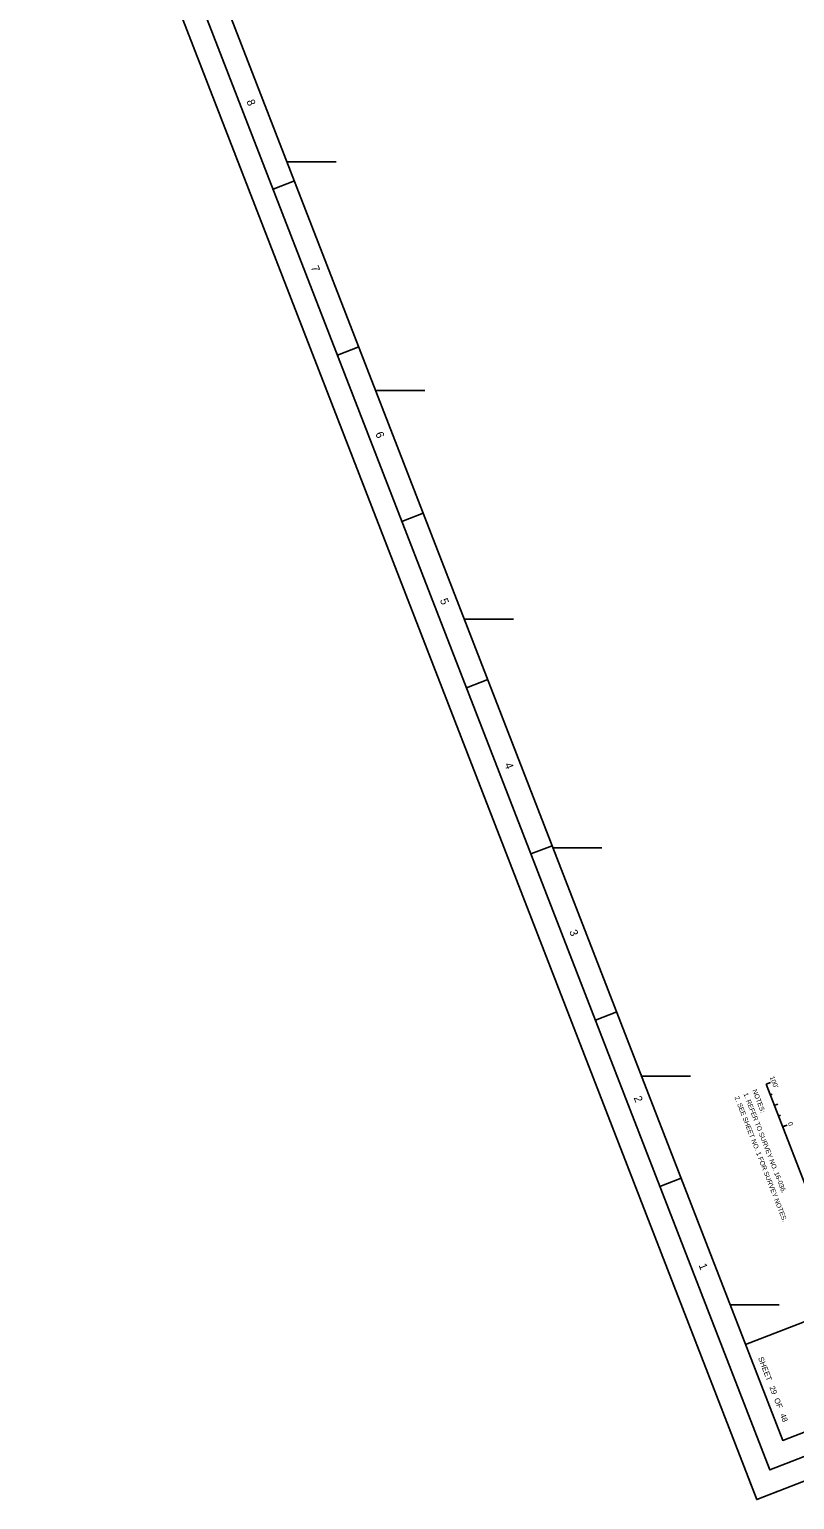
# Model space of a CAD drawing. Extents: x 587779 to 592541, y 824574 to 829906.
# Drawn here: x 587779 to 589454, y 824574 to 827790 of the extents above; entities that cross this region are included whole.
import ezdxf

# ---------------------------------------------------------------- set-up
doc = ezdxf.new("R2010")
doc.units = 0
for name, color, linetype in [('G-ANNO-NPLT', 7, 'Continuous'), ('G-ANNO-TEXT-DRWG', 7, 'Continuous'), ('G-ANNO-TEXT-TTLB', 7, 'Continuous'), ('G-ANNO-TTLB', 7, 'Continuous'), ('V-ANNO-NOTE', 7, 'Continuous'), ('V-TOPO-COOR-STAT', 7, 'Continuous')]:
    doc.layers.add(name, color=color, linetype=linetype)

msp = doc.modelspace()

# ---------------------------------------------------------------- linework, layer by layer
at = {"layer": 'G-ANNO-NPLT'}
msp.add_lwpolyline([(590949.1, 829906.3), (592540.6, 825804.2), (589370.9, 824574.4), (587779.3, 828676.5)], close=True, dxfattribs=at)
msp.add_lwpolyline([(589417.5, 824592.4), (589370.9, 824574.3), (589352.8, 824620.9)], dxfattribs=at)
at = {"layer": 'G-ANNO-TTLB'}
for p, q in [((588312.4, 827440.6), (588359.1, 827458.7)), ((588453.5, 827077), (588500.1, 827095.1)), ((588594.6, 826713.4), (588641.2, 826731.5)), ((588735.6, 826349.8), (588782.3, 826367.9)), ((592329.8, 826071.1), (589346.5, 824913.6)), ((588876.7, 825986.3), (588923.3, 826004.3)), ((589017.8, 825622.7), (589064.4, 825640.8)), ((589158.8, 825259.1), (589205.5, 825277.2))]:
    msp.add_line(p, q, dxfattribs=at)
for points in [[(587844, 828647.9), (589399.4, 824639.1), (592475.9, 825832.7), (590920.6, 829841.6)], [(592411.2, 825861.3), (590919.2, 829706.9), (587935.9, 828549.5), (589427.9, 824703.8)]]:
    msp.add_lwpolyline(points, close=True, dxfattribs=at)
at = {"layer": 'V-ANNO-NOTE'}
for p, q in [((589391.3, 825482.8), (589401.1, 825486.6)), ((589391.3, 825482.8), (589499.9, 825203.2)), ((589400.4, 825459.5), (589404.8, 825461.3)), ((589409.4, 825436.2), (589417.4, 825439.3)), ((589418.5, 825412.9), (589422.9, 825414.7)), ((589427.5, 825389.6), (589437.3, 825393.4)), ((589427.5, 825389.6), (589437.3, 825393.4)), ((589427.5, 825389.6), (589432.2, 825391.4))]:
    msp.add_line(p, q, dxfattribs=at)
at = {"layer": 'V-TOPO-COOR-STAT'}
for p, q in [((588343, 827500), (588450.3, 827500)), ((588537, 827000), (588644.3, 827000)), ((588731, 826500), (588838.3, 826500)), ((588925, 826000), (589032.3, 826000)), ((589119, 825500), (589226.3, 825500)), ((589313, 825000), (589420.3, 825000))]:
    msp.add_line(p, q, dxfattribs=at)

# ---------------------------------------------------------------- texts
at = {"layer": 'G-ANNO-TEXT-DRWG'}
msp.add_text(' 29          48', height=12, rotation=291.2052, dxfattribs=at).set_placement((589396.7, 824824.2))
at = {"layer": 'G-ANNO-TEXT-TTLB'}
msp.add_text('SHEET         OF', height=12, rotation=291.2052, dxfattribs=at).set_placement((589373.6, 824883.9))
at = {"layer": 'G-ANNO-TTLB'}
for s, p in [('8', (588254.1, 827632.6)), ('7', (588394.9, 827269.5)), ('6', (588536, 826905.9)), ('5', (588677.3, 826541.6)), ('4', (588818.6, 826182.2)), ('3', (588960.3, 825816.9)), ('2', (589101.3, 825453.5)), ('1', (589243.5, 825087))]:
    msp.add_text(s, height=17.5, rotation=291.2052, dxfattribs=at).set_placement(p)
at = {"layer": 'V-ANNO-NOTE'}
for s, height, p in [("100'", 10.42, (589399.1, 825498)), ('2. SEE SHEET NO. 1 FOR SURVEY NOTES.', 10.416, (589322.1, 825454.1)), ('1. REFER TO SURVEY NO. 16-036.', 10.416, (589341.6, 825461.7)), ('NOTES:', 10.42, (589361, 825469.2)), ('0', 10.4, (589438.7, 825397.9))]:
    msp.add_text(s, height=height, rotation=291.2052, dxfattribs=at).set_placement(p)

doc.saveas('drawing.dxf')
